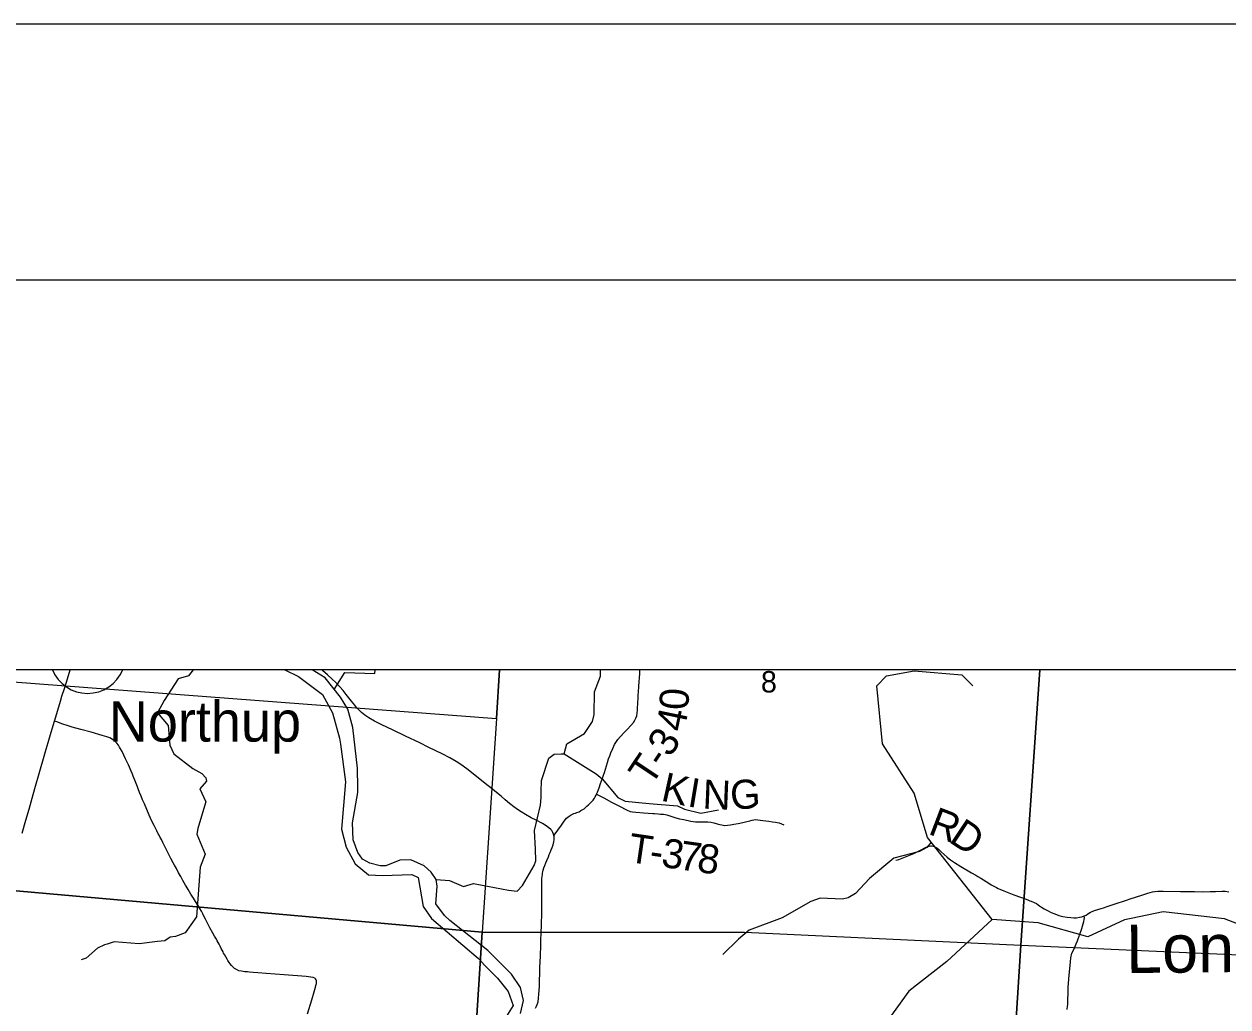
# Model space of a CAD drawing. Extents: x 396.2 to 468.4, y 232.6 to 279.1.
# Drawn here: x 418.928 to 421.28, y 277.199 to 279.121 of the extents above; entities that cross this region are included whole.
import ezdxf

# ---------------------------------------------------------------- set-up
doc = ezdxf.new("R2010")
doc.units = 0
for name, color, linetype in [('Default', 7, 'Continuous'), ('GM_X_County_Road', 7, 'Continuous'), ('GM_X_Major_River', 7, 'Continuous'), ('GM_X_Minor_River', 7, 'Continuous'), ('GM_X_Minor_River_Text', 7, 'Continuous'), ('GM_X_Section', 7, 'Continuous'), ('GM_X_Section_Text', 7, 'Continuous'), ('GM_X_Township_Road', 7, 'Continuous'), ('GM_X_Township_Road_Text', 7, 'Continuous'), ('GM_X_Unincorporated_Text', 7, 'Continuous'), ('SH_Border', 7, 'Continuous'), ('SH_Cut_Line', 7, 'Continuous'), ('TX_P_1', 7, 'Continuous')]:
    doc.layers.add(name, color=color, linetype=linetype)

msp = doc.modelspace()

# ---------------------------------------------------------------- linework, layer by layer
at = {"layer": 'Default'}
msp.add_line((419.1207, 277.8582), (418.9833, 277.8582), dxfattribs=at)
msp.add_lwpolyline([(421.9682, 277.8582), (415.7353, 277.8582)], dxfattribs=at)
for points in [[(419.857, 277.8582), (418.8124, 277.8582), (418.8114, 277.8417), (419.8508, 277.7629)], [(420.9126, 277.8582), (419.857, 277.8582), (419.8508, 277.7629), (419.823, 277.3452), (420.3357, 277.3452), (420.8756, 277.3198)], [(421.97, 277.8582), (420.9126, 277.8582), (420.8756, 277.3198), (421.9349, 277.2729), (421.9483, 277.4985)]]:
    msp.add_lwpolyline(points, close=True, dxfattribs=at)
msp.add_arc((419.052, 277.8867), 0.0744, 202.5634, 337.4366, dxfattribs=at)
at = {"layer": 'GM_X_County_Road'}
for points in [[(418.924, 277.539), (418.9316, 277.5646), (418.9376, 277.5861), (418.9436, 277.6076), (418.9487, 277.6263), (418.9585, 277.6601), (418.967, 277.6898), (418.9712, 277.7035), (418.9749, 277.7165), (418.9806, 277.7363), (418.9872, 277.7582), (418.9897, 277.7667), (418.9988, 277.797), (419.002, 277.8071), (419.0066, 277.8219), (419.0125, 277.8409), (419.0179, 277.8582)], [(419.9274, 277.1967), (419.9292, 277.2006), (419.9306, 277.2041), (419.932, 277.2095), (419.9331, 277.2167), (419.9338, 277.2241), (419.9344, 277.2315), (419.9348, 277.2396), (419.9351, 277.2495), (419.9352, 277.2538), (419.9354, 277.2619), (419.9358, 277.2762), (419.9367, 277.2985), (419.9375, 277.3209), (419.9378, 277.3314), (419.9381, 277.343), (419.9386, 277.3606), (419.9392, 277.3823), (419.9393, 277.3928), (419.9393, 277.4015), (419.9396, 277.4158), (419.9395, 277.4412), (419.9398, 277.4498), (419.9402, 277.4547), (419.9405, 277.4577), (419.9409, 277.4608), (419.9417, 277.4637), (419.9424, 277.4667), (419.9437, 277.4714), (419.9455, 277.476), (419.9474, 277.4812), (419.9492, 277.4858), (419.9522, 277.493), (419.954, 277.4971), (419.9556, 277.5012), (419.9576, 277.5065), (419.9595, 277.511), (419.9613, 277.5164), (419.9628, 277.5218), (419.9634, 277.5262), (419.9636, 277.5287), (419.9634, 277.5325), (419.963, 277.5345), (419.9625, 277.5368), (419.9612, 277.5403), (419.9588, 277.544), (419.9571, 277.546), (419.9529, 277.5497), (419.9478, 277.5534), (419.9408, 277.5576), (419.9281, 277.5642), (419.9187, 277.569), (419.9073, 277.5752), (419.8989, 277.5805), (419.8918, 277.5854), (419.8848, 277.5906), (419.8766, 277.5971), (419.868, 277.6042), (419.8598, 277.611), (419.8509, 277.6182), (419.8429, 277.6247), (419.8287, 277.6362), (419.8121, 277.6498), (419.7931, 277.6649), (419.7815, 277.6733), (419.7721, 277.6793), (419.7596, 277.6865), (419.7447, 277.6941), (419.7189, 277.7066), (419.701, 277.7153), (419.6731, 277.7288), (419.6479, 277.741), (419.6271, 277.7508), (419.6127, 277.758), (419.6014, 277.7644), (419.5936, 277.7695), (419.5874, 277.7746), (419.5812, 277.7806), (419.5775, 277.7848), (419.5739, 277.789), (419.5677, 277.7969), (419.5624, 277.8036), (419.5573, 277.8101), (419.5512, 277.8178), (419.5447, 277.8253), (419.5369, 277.8334), (419.5297, 277.8402), (419.521, 277.8482), (419.5112, 277.8569), (419.5098, 277.8582)]]:
    msp.add_lwpolyline(points, dxfattribs=at)
at = {"layer": 'GM_X_Major_River'}
for points in [[(419.4374, 277.8582), (419.4638, 277.8451), (419.5112, 277.81), (419.5303, 277.774), (419.544, 277.7247), (419.5463, 277.713), (419.556, 277.639), (419.548, 277.5468), (419.5571, 277.5115), (419.5747, 277.4793), (419.6009, 277.4578), (419.6281, 277.456), (419.6857, 277.4585), (419.6979, 277.4525), (419.7079, 277.3956), (419.7242, 277.3721), (419.8158, 277.2939), (419.8283, 277.2803), (419.853, 277.2557), (419.8739, 277.2292), (419.8834, 277.2023), (419.8642, 277.1711)], [(419.5803, 277.6277), (419.5794, 277.6661), (419.5705, 277.7453), (419.5602, 277.7813), (419.5461, 277.8048), (419.516, 277.8423), (419.491, 277.8582)], [(419.8979, 277.1864), (419.9039, 277.2119), (419.8977, 277.2373), (419.8802, 277.2634), (419.8339, 277.3095), (419.7599, 277.3684), (419.7492, 277.3779), (419.7325, 277.4006), (419.735, 277.4355), (419.7331, 277.4484), (419.7232, 277.4628), (419.7095, 277.4749), (419.6837, 277.4866), (419.6618, 277.4861), (419.6349, 277.475), (419.6235, 277.4753), (419.6035, 277.4806), (419.589, 277.4881), (419.5799, 277.5014), (419.5707, 277.526), (419.5695, 277.5594), (419.58, 277.6182), (419.5803, 277.6277)]]:
    msp.add_lwpolyline(points, dxfattribs=at)
at = {"layer": 'GM_X_Minor_River'}
for points in [[(419.2586, 277.8582), (419.2492, 277.8463), (419.2287, 277.8406), (419.2018, 277.7983), (419.1889, 277.774), (419.2097, 277.7497), (419.2124, 277.7113), (419.2207, 277.6938), (419.2575, 277.6657), (419.2749, 277.6558), (419.2832, 277.6471), (419.2844, 277.6406), (419.2711, 277.6258), (419.2832, 277.6003), (419.2688, 277.5524), (419.2677, 277.5479), (419.2654, 277.5372), (419.2817, 277.4981), (419.2722, 277.4726), (419.2649, 277.3752), (419.2426, 277.344), (419.224, 277.3372), (419.2134, 277.336), (419.2028, 277.3288), (419.1884, 277.3272), (419.1527, 277.3226), (419.1042, 277.3268), (419.0902, 277.3222), (419.0849, 277.3207), (419.0712, 277.3142), (419.0492, 277.2944), (419.0397, 277.2913)], [(419.534, 277.8197), (419.5548, 277.853), (419.6133, 277.8509), (419.6139, 277.8582)], [(419.7331, 277.4484), (419.7593, 277.4465), (419.7866, 277.4347), (419.8059, 277.4408), (419.8745, 277.4276), (419.8912, 277.4253), (419.9014, 277.4364), (419.9242, 277.4755), (419.9276, 277.4851), (419.9272, 277.5079), (419.9254, 277.5444), (419.9371, 277.5934), (419.9379, 277.6086), (419.9379, 277.6197), (419.9387, 277.6417), (419.9531, 277.6858), (419.9637, 277.6931), (419.977, 277.6942), (419.9834, 277.6939), (419.9883, 277.7136), (420.0229, 277.7338), (420.0384, 277.7574), (420.0418, 277.7711), (420.0422, 277.8152), (420.0544, 277.8456), (420.0544, 277.8582)], [(420.8193, 277.3705), (420.693, 277.5303), (420.6671, 277.6174), (420.6048, 277.7136), (420.5942, 277.8267), (420.6129, 277.8466), (420.667, 277.8562), (420.7598, 277.8486), (420.7817, 277.8272)], [(419.9834, 277.6939), (420.0455, 277.6547), (420.0572, 277.645), (420.0878, 277.6089), (420.1021, 277.6015), (420.1492, 277.597), (420.2046, 277.5925), (420.2181, 277.5858), (420.2503, 277.5778), (420.2846, 277.5845)], [(420.6999, 277.5216), (420.6915, 277.511), (420.6774, 277.5032), (420.627, 277.4902), (420.5794, 277.4505), (420.5524, 277.4213), (420.5382, 277.4127), (420.5268, 277.4102), (420.4831, 277.4116), (420.4652, 277.4054), (420.4089, 277.3738), (420.3443, 277.3493), (420.3236, 277.3317), (420.2931, 277.3021)], [(419.7083, 277.4792), (419.7083, 277.4793)], [(419.7087, 277.4791), (419.7087, 277.4791)], [(419.735, 277.4685), (419.7349, 277.4685)], [(421.3949, 277.3244), (421.2732, 277.3715), (421.1535, 277.3849), (421.0906, 277.3722), (421.0777, 277.3694), (421.006, 277.3365), (420.9093, 277.3634), (420.8192, 277.3705), (420.7307, 277.2881), (420.6567, 277.2301), (420.5784, 277.1217), (420.5416, 277.0902), (420.4632, 277.0713), (420.3933, 277.0171), (420.3603, 276.9633)]]:
    msp.add_lwpolyline(points, dxfattribs=at)
at = {"layer": 'GM_X_Section'}
for points in [[(418.8114, 277.8417), (419.8508, 277.7629), (419.823, 277.3452), (418.7866, 277.4374)], [(418.7866, 277.4374), (419.823, 277.3452), (419.7599, 276.357), (418.7224, 276.4162)], [(420.8756, 277.3198), (420.8122, 276.3213), (419.7599, 276.357), (419.823, 277.3452), (420.3357, 277.3452)], [(421.9349, 277.2729), (421.9181, 277.0115), (421.8725, 276.2694), (420.8243, 276.321), (420.8122, 276.3213), (420.8756, 277.3198)]]:
    msp.add_lwpolyline(points, close=True, dxfattribs=at)
at = {"layer": 'GM_X_Township_Road'}
for points in [[(419.963, 277.5345), (419.9692, 277.5428), (419.9721, 277.5468), (419.9766, 277.5528), (419.9832, 277.5624), (419.9878, 277.5681), (419.9901, 277.5703), (419.9928, 277.5724), (419.9966, 277.5745), (419.9993, 277.5759), (420.0017, 277.5771), (420.005, 277.5782), (420.0081, 277.5791), (420.0123, 277.581), (420.016, 277.5831), (420.0219, 277.5867), (420.0251, 277.5893), (420.0277, 277.5918), (420.0305, 277.5942), (420.0342, 277.5976), (420.0382, 277.6021), (420.0395, 277.6037), (420.0412, 277.6056), (420.0422, 277.6073), (420.0439, 277.6103), (420.0455, 277.6135), (420.0464, 277.6155), (420.048, 277.6191), (420.0499, 277.6241), (420.0513, 277.6276), (420.0542, 277.6358), (420.0579, 277.6464), (420.0598, 277.6521), (420.0616, 277.6576), (420.0655, 277.6707), (420.0675, 277.6768), (420.0699, 277.6842), (420.0722, 277.6902), (420.0743, 277.6957), (420.0779, 277.7043), (420.0816, 277.7121), (420.0851, 277.718), (420.0879, 277.722), (420.093, 277.7282), (420.0998, 277.7354), (420.1068, 277.7425), (420.1132, 277.7492), (420.1183, 277.7554), (420.1214, 277.7601), (420.1234, 277.764), (420.1248, 277.7681), (420.1257, 277.7737), (420.1264, 277.7799), (420.1267, 277.7851), (420.1269, 277.7905), (420.1272, 277.7961), (420.1274, 277.8004), (420.1275, 277.8028), (420.128, 277.8092), (420.1284, 277.8146), (420.1292, 277.8266), (420.131, 277.851), (420.1312, 277.8582)], [(419.4982, 277.241), (419.4992, 277.2451), (419.4995, 277.2481), (419.4993, 277.2504), (419.4985, 277.2526), (419.4976, 277.254), (419.4957, 277.2554), (419.4925, 277.2568), (419.4882, 277.2576), (419.479, 277.2589), (419.4362, 277.2618), (419.4007, 277.2647), (419.3847, 277.2659), (419.3755, 277.2666), (419.3682, 277.2672), (419.3644, 277.2676), (419.3591, 277.2682), (419.3527, 277.2692), (419.3478, 277.2701), (419.3427, 277.2722), (419.3389, 277.2747), (419.3355, 277.2779), (419.3333, 277.2801), (419.3305, 277.2834), (419.3286, 277.2859), (419.3272, 277.288), (419.3259, 277.2901), (419.3244, 277.2928), (419.322, 277.297), (419.3193, 277.302), (419.3178, 277.3047), (419.3167, 277.3069), (419.3133, 277.3134), (419.3108, 277.3183), (419.3089, 277.3221), (419.3054, 277.3286), (419.3036, 277.3318), (419.3001, 277.3377), (419.2967, 277.3435), (419.291, 277.3538), (419.2882, 277.3594), (419.2851, 277.3655), (419.2824, 277.3709), (419.2801, 277.3755), (419.2772, 277.381), (419.2743, 277.3864), (419.271, 277.392), (419.2674, 277.3982), (419.263, 277.4053), (419.2589, 277.4118), (419.254, 277.4198), (419.2486, 277.4288), (419.2448, 277.4352), (419.2435, 277.4373), (419.2409, 277.4419), (419.2383, 277.4465), (419.2341, 277.454), (419.2299, 277.4617), (419.2256, 277.4697), (419.2219, 277.4765), (419.2192, 277.4813), (419.2149, 277.4895), (419.2123, 277.4945), (419.2081, 277.5028), (419.2037, 277.5116), (419.1989, 277.5208), (419.1961, 277.5263), (419.1939, 277.5308), (419.1916, 277.5352), (419.1902, 277.538), (419.1874, 277.5435), (419.1846, 277.549), (419.1819, 277.5542), (419.1785, 277.5611), (419.1749, 277.568), (419.1721, 277.5744), (419.1677, 277.5854), (419.163, 277.5963), (419.1595, 277.6042), (419.1566, 277.6113), (419.1537, 277.6186), (419.151, 277.6255), (419.1494, 277.6296), (419.1456, 277.6395), (419.1413, 277.6504), (419.1397, 277.6545), (419.1373, 277.6602), (419.1318, 277.6726), (419.1263, 277.6843), (419.123, 277.6912), (419.1194, 277.6986), (419.1166, 277.7039), (419.1145, 277.7074), (419.1125, 277.7108), (419.1091, 277.7152), (419.1052, 277.719), (419.1007, 277.7222), (419.0953, 277.7252), (419.0897, 277.7275), (419.0807, 277.7302), (419.059, 277.7363), (419.0387, 277.7418), (419.0218, 277.7464), (419.0123, 277.7495), (419.0039, 277.7522), (418.9919, 277.7565), (418.9872, 277.7582)], [(420.0464, 277.6155), (420.0515, 277.6128), (420.0531, 277.612), (420.0557, 277.6106), (420.0606, 277.6079), (420.0753, 277.5999), (420.0898, 277.5925), (420.1061, 277.5839), (420.1118, 277.5816), (420.1165, 277.5807), (420.1233, 277.5802), (420.1382, 277.5788), (420.1561, 277.5777), (420.1599, 277.5774), (420.1665, 277.577), (420.1713, 277.5764), (420.1769, 277.5758), (420.1835, 277.5746), (420.1913, 277.5724), (420.2014, 277.5692), (420.2084, 277.5672), (420.2167, 277.5658), (420.2308, 277.5626), (420.2397, 277.5613), (420.2475, 277.5611), (420.2558, 277.5612), (420.2636, 277.5609), (420.2699, 277.5604), (420.2757, 277.5594), (420.2823, 277.5573), (420.287, 277.556), (420.2911, 277.5551), (420.2963, 277.5542), (420.3019, 277.5544), (420.308, 277.5553), (420.3147, 277.5566), (420.3229, 277.5579), (420.3324, 277.5599), (420.34, 277.5615), (420.3457, 277.5632), (420.3505, 277.5645), (420.3538, 277.5652), (420.3572, 277.5654), (420.3617, 277.5652), (420.3662, 277.5645), (420.3715, 277.5637), (420.3771, 277.563), (420.3828, 277.5622), (420.3901, 277.5613), (420.3957, 277.5605), (420.3995, 277.5599), (420.403, 277.5589), (420.4076, 277.5571), (420.4123, 277.555)], [(420.6313, 277.4862), (420.6342, 277.4868), (420.6372, 277.4878), (420.6436, 277.4902), (420.6469, 277.4915), (420.666, 277.4992), (420.6804, 277.5065), (420.6891, 277.5112), (420.6937, 277.5131), (420.6985, 277.5143), (420.701, 277.5144), (420.7039, 277.5137), (420.7074, 277.5123), (420.7112, 277.51), (420.7151, 277.5068), (420.7197, 277.5026), (420.7312, 277.4921), (420.735, 277.489), (420.7379, 277.4867), (420.7455, 277.4814), (420.7583, 277.4737), (420.7791, 277.4614), (420.7872, 277.4567), (420.7915, 277.4541), (420.7972, 277.4507), (420.8021, 277.4478), (420.8076, 277.4443), (420.8129, 277.441), (420.8173, 277.4382), (420.8226, 277.4351), (420.8249, 277.434), (420.8276, 277.4326), (420.831, 277.4311), (420.8344, 277.4297), (420.8424, 277.4264), (420.8619, 277.4185), (420.8747, 277.4137), (420.8835, 277.4105), (420.8887, 277.4086), (420.8927, 277.407), (420.8956, 277.406), (420.9014, 277.4036), (420.9057, 277.4012), (420.9093, 277.3988), (420.9117, 277.3971), (420.9154, 277.3945), (420.9211, 277.3908), (420.9271, 277.3876), (420.9346, 277.3842), (420.9417, 277.381), (420.9497, 277.3781), (420.9575, 277.3762), (420.9661, 277.3747), (420.9733, 277.3741), (420.9787, 277.3738), (420.9838, 277.3738), (420.9897, 277.3746), (420.9944, 277.3757), (420.9991, 277.3772)], [(420.9991, 277.3772), (421.0027, 277.379), (421.0062, 277.3812), (421.0112, 277.3843), (421.0144, 277.3861), (421.019, 277.3878), (421.026, 277.39), (421.0325, 277.392), (421.0367, 277.3933), (421.0438, 277.3955), (421.0497, 277.3975), (421.0574, 277.3999), (421.0815, 277.408), (421.0886, 277.4103), (421.1117, 277.4177), (421.1235, 277.4215), (421.1323, 277.4242), (421.1371, 277.4252), (421.1432, 277.4256), (421.1532, 277.4257), (421.1873, 277.4252), (421.2004, 277.4249), (421.2146, 277.4247), (421.2295, 277.4246), (421.2451, 277.4248), (421.2555, 277.4251), (421.2687, 277.4256), (421.2742, 277.4253), (421.2815, 277.4244)], [(420.9661, 277.1943), (420.9668, 277.2008), (420.9671, 277.2036), (420.9672, 277.2095), (420.9679, 277.2309), (420.968, 277.2387), (420.9683, 277.2446), (420.969, 277.2542), (420.9722, 277.2875), (420.973, 277.2952), (420.9736, 277.2987), (420.9742, 277.3013), (420.9752, 277.3041), (420.978, 277.3102), (420.9807, 277.3159), (420.9834, 277.3228), (420.9857, 277.3286), (420.9871, 277.3327), (420.9891, 277.3378), (420.99, 277.3401), (420.9923, 277.3465), (420.9943, 277.3524), (420.9959, 277.3571), (420.9984, 277.366), (420.9992, 277.3701), (420.9994, 277.3736), (420.9991, 277.3772)], [(419.4819, 277.1855), (419.4903, 277.2135), (419.4916, 277.2177), (419.4934, 277.2242), (419.4975, 277.2379), (419.4982, 277.241)]]:
    msp.add_lwpolyline(points, dxfattribs=at)
at = {"layer": 'SH_Border'}
msp.add_lwpolyline([(397.7027, 278.6206), (429.7027, 278.6206), (429.7027, 257.6206), (397.7027, 257.6206)], close=True, dxfattribs=at)
at = {"layer": 'SH_Cut_Line'}
msp.add_lwpolyline([(396.2027, 257.1206), (430.2027, 257.1206), (430.2027, 279.1206), (396.2027, 279.1206)], close=True, dxfattribs=at)
msp.add_lwpolyline([(422.4135, 277.8582), (413.8513, 277.8582)], dxfattribs=at)
at = {"layer": 'TX_P_1'}
msp.add_line((427.4513, 277.8582), (413.8513, 277.8582), dxfattribs=at)

# ---------------------------------------------------------------- texts
at = {"layer": 'GM_X_Minor_River_Text'}
msp.add_text('Long', height=0.0947, rotation=0.5112, dxfattribs=at).set_placement((421.0812, 277.2655))
at = {"layer": 'GM_X_Section_Text'}
msp.add_text('8', height=0.0419, rotation=0, dxfattribs=at).set_placement((420.3675, 277.814))
at = {"layer": 'GM_X_Township_Road_Text'}
for s, rotation, p in [('0', 86.9958, (420.2255, 277.7788)), ('4', 78.2462, (420.2172, 277.7352)), ('3', 57.8282, (420.1904, 277.6852)), ('T', 56.159, (420.1527, 277.629)), ('-', 56.2662, (420.1765, 277.6644)), ('K', 347.5755, (420.1703, 277.603)), ('I', 350.5159, (420.2222, 277.5917)), ('N', 357.5849, (420.2528, 277.587)), ('G', 3.4121, (420.3091, 277.585)), ('R', 339.131, (420.6922, 277.5381)), ('D', 326.4024, (420.7328, 277.523)), ('T', 351.6566, (420.1058, 277.4831)), ('3', 351.7154, (420.171, 277.4736)), ('7', 351.8574, (420.2057, 277.4685)), ('8', 352.3329, (420.2409, 277.4635)), ('-', 351.663, (420.1478, 277.477))]:
    msp.add_text(s, height=0.0568, rotation=rotation, dxfattribs=at).set_placement(p)
at = {"layer": 'GM_X_Unincorporated_Text'}
msp.add_text('Northup', height=0.07898, rotation=0, dxfattribs=at).set_placement((419.0934, 277.718))

doc.saveas('drawing.dxf')
